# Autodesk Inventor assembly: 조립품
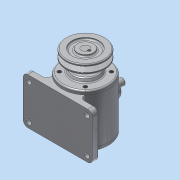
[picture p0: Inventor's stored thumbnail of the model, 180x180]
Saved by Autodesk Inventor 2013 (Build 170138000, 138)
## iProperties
Created: 2015-08
Part Number: 조립품
Document SubType Name: Assembly
Designer: dgall
Mass: 2990.33 g
Surface Area: 2017.36 cm^2
Volume: 938.374 cm^3
Density: 3.18671 g/cm^3
Author: dgall
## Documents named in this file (14)
- C:\Users\dgall\Desktop\350805V1036\답안\조립품.iam
- C:\Users\dgall\Desktop\350805V1036\Part\KS B 1028  - 납작점M4x5.ipt
- C:\Users\dgall\Desktop\350805V1036\Part\KS B 1311 - 5 x 5 x 18I.ipt
- C:\Users\dgall\Desktop\350805V1036\Part\M4-소켓머리.ipt
- C:\Users\dgall\Desktop\350805V1036\Part\V-벨트풀리.ipt
- C:\Users\dgall\Desktop\350805V1036\Part\뒷커버.ipt
- C:\Users\dgall\Desktop\350805V1036\Part\베어링 6203.ipt
- C:\Users\dgall\Desktop\350805V1036\Part\본체.ipt
- C:\Users\dgall\Desktop\350805V1036\Part\부시.ipt
- C:\Users\dgall\Desktop\350805V1036\Part\슬라이더.ipt
- C:\Users\dgall\Desktop\350805V1036\Part\앞커버.ipt
- C:\Users\dgall\Desktop\350805V1036\Part\오일실.ipt
- C:\Users\dgall\Desktop\350805V1036\Part\축.ipt
- C:\Users\dgall\Desktop\350805V1036\Part\스프링1 [가변부품].ipt
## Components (14 placed, 6 different names)
1. KS B 1028 납작점 - 미터 납작점M4x5:1
2. KS B 1311 (I) 5 x 5 x 18:1
3. V-벨트풀리:1 — 플러쉬:1
4. 7-베어링 6203:1
5. 8-오일실:1
6. 7-베어링 6203:2
7. 9-M4-소켓머리:1
8. 9-M4-소켓머리:2
9. 9-M4-소켓머리:3
10. 9-M4-소켓머리:4
11. 9-M4-소켓머리:5
12. 9-M4-소켓머리:6
13. 9-M4-소켓머리:7
14. 9-M4-소켓머리:8
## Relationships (1: Flush 1)
- 플러쉬:1 [Flush]: V-벨트풀리:1
